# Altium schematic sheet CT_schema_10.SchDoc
size 274 x 160 mm
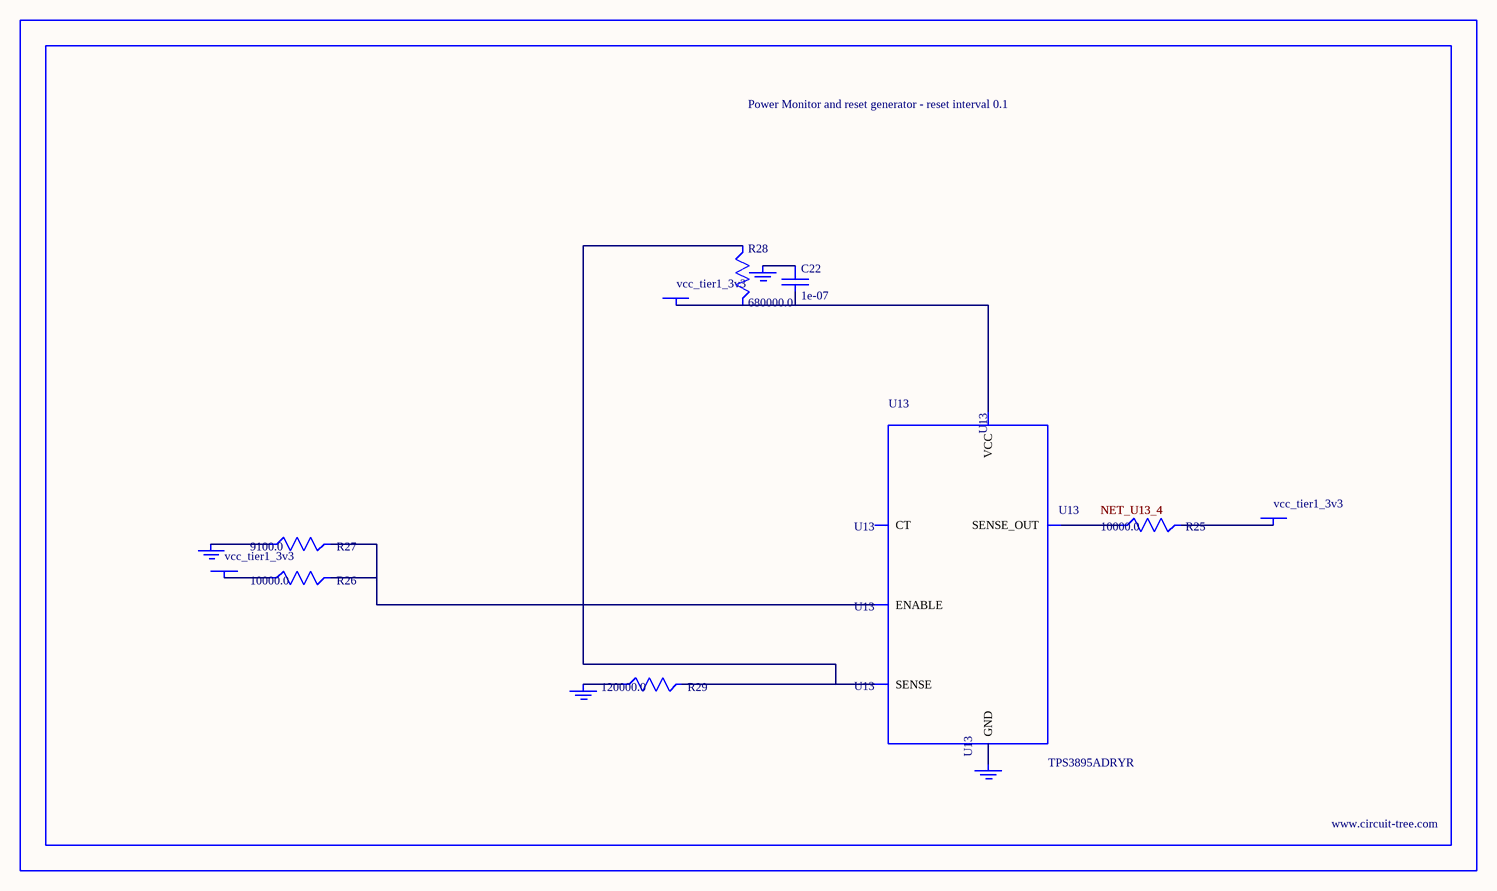
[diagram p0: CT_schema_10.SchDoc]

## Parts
BORDER9  (no value)
C22  1e-07  [C0402]
GND_INSTANCE_9_0  (no value)
GND_INSTANCE_9_1  (no value)
GND_INSTANCE_9_2  (no value)
GND_INSTANCE_9_3  (no value)
POWER_INSTANCE_9_0  vcc_tier1_3v3
POWER_INSTANCE_9_1  vcc_tier1_3v3
POWER_INSTANCE_9_2  vcc_tier1_3v3
R25  10000.0  [R0603]
R26  10000.0  [R0603]
R27  9100.0  [R0603]
R28  680000.0  [R0603]
R29  120000.0  [R0603]
U13  TPS3895ADRYR  [SON-6]

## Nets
NetC22_1: C22.1 GND_INSTANCE_9_2.0(GND)
NetC22_2: C22.2 POWER_INSTANCE_9_2.0(PWR) R28.2 U13.6(VCC)
NetGND_INSTANCE_9_0_0: GND_INSTANCE_9_0.0(GND) R27.1
NetGND_INSTANCE_9_1_0: GND_INSTANCE_9_1.0(GND) R29.1
NetGND_INSTANCE_9_3_0: GND_INSTANCE_9_3.0(GND) U13.2(GND)
NetPOWER_INSTANCE_9_0_0: POWER_INSTANCE_9_0.0(PWR) R26.1
NetPOWER_INSTANCE_9_1_0: POWER_INSTANCE_9_1.0(PWR) R25.2
NetR25_1: R25.1 U13.4(SENSE_OUT)
NetR26_2: R26.2 R27.2 U13.1(ENABLE)
NetR28_1: R28.1 R29.2 U13.3(SENSE)

Not connected (* = marked no-connect by the designer): U13 5(CT)

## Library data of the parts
BORDER9 = BORDER_PAGE9
C22 = C0402C104K3RACTU
GND_INSTANCE_9_0-GND_INSTANCE_9_3 = GND
POWER_INSTANCE_9_0-POWER_INSTANCE_9_2 = PWR
R25 R26 = RC0603JR-0710KL
R27 = RC0603JR-079K1L
R28 = RC0603JR-07680KL
R29 = RC0603JR-07120KL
